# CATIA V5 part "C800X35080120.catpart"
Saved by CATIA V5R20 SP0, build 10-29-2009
Part number: C800X35080120
Source: Unknown
Property "A": "90"
Property "ARTICLENO": "C800X35080120"
Property "B": "45"
Property "BOMINFO": "C800X35080120"
Property "C": "124"
Property "CA": "C800X35080120"
Property "D1": "170"
Property "DES": "ROTATING EYEBOLT WITH RING Ton 35,0 M80x120"
Property "E": "165"
Property "H": "333"
Property "L": "120"
Property "LINA": "C800X35080120"
Property "NB": "C800X35080120"
Property "NBSYN": "$CODE."
Property "NN": "C800X"
Property "NT": "Rotating eyebolt with ring"
Property "SIZE": "M80"
Property "SUPPLIER": "CF"
Property "SW": "134"
Property "WEIGHT": "29000"
Property "WLL": "35.00"
Bounding box of the stored display mesh (mm): x -90 to 90, y -120 to 378, z -85 to 85
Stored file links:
  C:\Users\Utente\Desktop\3D files 800X\C800X35080120.catpart
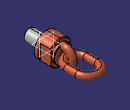
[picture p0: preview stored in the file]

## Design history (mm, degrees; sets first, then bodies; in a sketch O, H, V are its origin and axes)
Body1 "Geometry.1" (main body)
  Solid1 "C800X35080120.catpart": solid without history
